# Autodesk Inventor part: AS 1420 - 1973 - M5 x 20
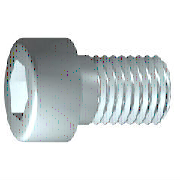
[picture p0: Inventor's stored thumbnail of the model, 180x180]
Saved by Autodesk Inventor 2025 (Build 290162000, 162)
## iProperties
Created: 2024-01
Part Number: AS 1420 - 1973 - M5 x 20
Material: Acciaio, Dolce
Description: Viti con esagono incassato metriche ISO
Document SubType Name: Modeling
Standard: AS 1420 - 1973
Designer: R5800u
Standards Organization: AS
Language: it-IT
Size Designation: M5 x 20
Categories: <MemberInstance><Categories><Category DisplayName="Elementi di fissaggio" InternalName="e4da775c-781d-43d5-af7c-5136215cf5a6" Mnemonic="FSTN"><Category DisplayN
Density: 7.85 g/cm^3
Appearance: Semilucidato
IsCustomPart: 0
Author: R5800u
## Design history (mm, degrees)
body "Solid1"
revolve "Corpo" stored, may be unused: angle "d10" = 90 deg
sketch "Schizzo2"
  geometry: L1 (0, -5.95)-(0, 5.95) reference; L2 (-5.95, 0)-(5.95, 0) reference; L3 (2.309, 0)-(1.155, -2); L4 (1.155, -2)-(-1.155, -2); L5 (-1.155, -2)-(-2.309, 0); L6 (-2.309, 0)-(-1.155, 2); L7 (-1.155, 2)-(1.155, 2); L8 (1.155, 2)-(2.309, 0); 2 further points
  constraints: 12 end point, 1 coincident, 1 horizontal alignment, 1 point on line, 12 other
extrude "Intaglio" join sketch "Schizzo2" stored distance "d11" = 10; taper "d12" = 0 deg
workplane "Work Plane1"
fillet "Fillet2" dims "d30" = 0.1 (= R)
fillet "Raccordo1" dims "d17" = 0.5 (= RR)
feature "Filettatura" dims "d13" = 16 (= GEL), "d14" = 0
chamfer "Smusso1" distance "d15" = 0.49076 (= -0.5 x SPD + 0.5 x GD); stored, may be unused: second distance "d16" = 0.49076 (= GUL), angle "d27" = 45 deg
sketch "Schizzo1"
  geometry: L1 (-1.167, 0)-(20, 0); L2 (20, 0)-(20, 2.5); L3 (20, 2.5)-(4, 2.5); L4 (4, 2.5)-(3.509, 2.5); L5 (3.509, 2.5)-(0, 2.5); L6 (0, 2.5)-(0, 4.25); L7 (0, 4.25)-(-5, 4.25); L8 (-5, 4.25)-(-5, 2.309); L9 (-5, 2.309)-(-2.5, 2.309); L10 (-2.5, 2.309)-(-1.167, 0); L11 (-10, 0)-(25, 0) reference; L12 (0, -0.85)-(0, 5.1) reference; L13 (4, 2.5)-(0, 2.5)
  constraints: 22 end point, 6 parallel, 2 collinear, 2 perpendicular, 1 horizontal, 1 point on line
  dimensions: "d1" = 16 distance from line of L3.end L2 (= GEL); "d2" = 0.49086 distance of L4.end L3.end (computed from GAL); "d3" = 5 distance between parallel lines of L8 L6 (= KOH); "d4" = 2.5 distance of L8.end L9.end (= INTI); "d5" = 60 deg angle of L10 L1; "d6" = 5 diameter of L3 L1 (= GD); "d7" = 5 diameter of L5 L1 (= BDM); "d8" = 4.6188 diameter of L9 L1 (= 1.1547 x SW); "d9" = 8.5 diameter of L7 L1 (= KOD); "d26" = 20 distance between parallel lines of L12 L2 (= NLG)
other parameters: "GD" = 5 (= NND) [user parameter; used in 2 equation terms], "NLG" = 20 [user parameter; used in 1 equation term], "GEL" = 16 [user parameter; used in 2 equation terms], "KOD" = 8.5 [user parameter; used in 1 equation term], "KOH" = 5 (= NND) [user parameter; used in 1 equation term], "INTI" = 2.5 [user parameter; used in 1 equation term], "GAL" = 0.49076 (= 0.61345 x PTC) [user parameter; used in 1 equation term], "GUL" = 0.49076 (= 0.61345 x PTC) [user parameter; used in 1 equation term], "BDM" = 5 (= NND) [user parameter; used in 1 equation term], "SW" = 4 [user parameter; used in 2 equation terms], "RR" = 0.5 (= 0.1 x NND) [user parameter; used in 1 equation term], "SPD" = 4.01848 (= NND - 1.2269 x PTC) [user parameter; used in 1 equation term], "d19" = 0, "d28" = 0, "d29" = 0, "R" = 0.1 [user parameter; used in 1 equation term], "PHH" = 0.13 [user parameter], "GD1" = 4.01848 (= THREADDIA - 1.2269 x PTC) [user parameter], "THREADDIA" = 5 [user parameter; used in 1 equation term], "FAWI" = 45 deg [user parameter], "TPU" = 12.5 (computed from PTC) [user parameter], "PTC" = 0.8 [user parameter; used in 5 equation terms], "KOH1" = 4.5 [user parameter], "NND" = 5 [user parameter; used in 5 equation terms], "TOA" = 30 deg [user parameter], "E0" = 4.62 (= 1.155 x SW) [user parameter]
